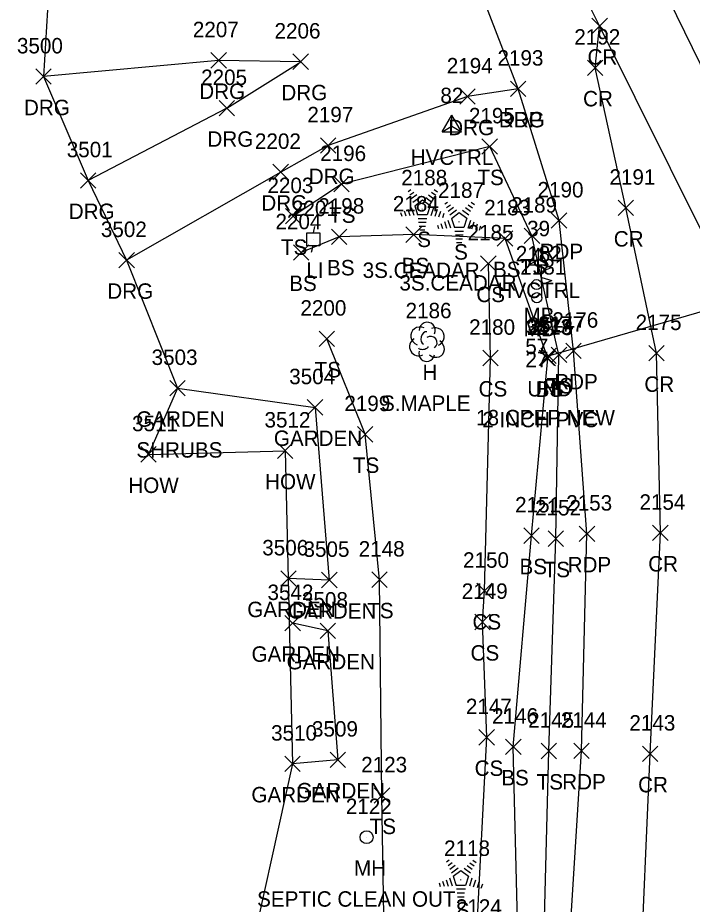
# Model space of a CAD drawing. Extents: x 1461855 to 1464118, y 556196 to 557441.
# Drawn here: x 1461866.4 to 1461953.7, y 556504.3 to 556619.2 of the extents above; entities that cross this region are included whole.
import ezdxf

# ---------------------------------------------------------------- set-up
doc = ezdxf.new("R2010")
doc.units = 0
for name, color, linetype in [('C_A', 7, 'Continuous'), ('C_I', 7, 'Continuous'), ('CPSM', 7, 'Continuous'), ('D_A', 7, 'Continuous'), ('D_C', 7, 'Continuous'), ('D_I', 7, 'Continuous'), ('D_TIC', 7, 'Continuous'), ('DCP', 7, 'Continuous'), ('L_A', 7, 'Continuous'), ('L_C', 7, 'Continuous'), ('L_I', 7, 'Continuous'), ('L_TIC', 7, 'Continuous'), ('LAPB', 7, 'Continuous'), ('LBC', 7, 'Continuous'), ('LELB', 7, 'Continuous'), ('LMB', 7, 'Continuous'), ('LSOGP', 7, 'Continuous'), ('LTC', 7, 'Continuous'), ('LTD', 7, 'Continuous'), ('P_A', 7, 'Continuous'), ('P_I', 7, 'Continuous'), ('P_TIC', 7, 'Continuous'), ('PET', 7, 'Continuous'), ('PRC', 7, 'Continuous'), ('R_A', 7, 'Continuous'), ('R_I', 7, 'Continuous'), ('R_TIC', 7, 'Continuous'), ('RDG', 7, 'Continuous'), ('U_A', 7, 'Continuous'), ('U_C', 7, 'Continuous'), ('U_I', 7, 'Continuous'), ('ULP', 7, 'Continuous'), ('UUMH', 7, 'Continuous')]:
    doc.layers.add(name, color=color, linetype=linetype)

msp = doc.modelspace()

# ---------------------------------------------------------------- linework, layer by layer
at = {"layer": 'CPSM'}
for p, q in [((1461921.33, 556604.38), (1461922.58, 556606.54)), ((1461923.83, 556604.38), (1461922.58, 556606.54)), ((1461922.58, 556605.1), (1461922.58, 556606.54)), ((1461921.33, 556604.38), (1461922.58, 556605.1)), ((1461922.58, 556605.1), (1461922.58, 556605.1)), ((1461922.58, 556605.1), (1461923.83, 556604.38)), ((1461921.33, 556604.38), (1461923.83, 556604.38)), ((1461932.57, 556587.14), (1461933.82, 556589.3)), ((1461935.07, 556587.14), (1461933.82, 556589.3)), ((1461933.82, 556587.86), (1461933.82, 556589.3)), ((1461932.57, 556587.14), (1461933.82, 556587.86)), ((1461933.82, 556587.86), (1461933.82, 556587.86)), ((1461933.82, 556587.86), (1461935.07, 556587.14)), ((1461932.57, 556587.14), (1461935.07, 556587.14))]:
    msp.add_line(p, q, dxfattribs=at)
at = {"layer": 'D_TIC'}
for points in [[(1461933.9, 556574.12), (1461935.9, 556576.12)], [(1461935.9, 556574.12), (1461933.9, 556576.12)], [(1461934.12, 556574.37), (1461936.12, 556576.37)], [(1461936.12, 556574.37), (1461934.12, 556576.37)]]:
    msp.add_lwpolyline(points, dxfattribs=at)
at = {"layer": 'DCP'}
msp.add_lwpolyline([(1461935.12, 556575.37), (1461973.52, 556586.51)], dxfattribs=at)
at = {"layer": 'L_TIC'}
for points in [[(1461926.5, 556601.48), (1461928.5, 556603.48)], [(1461928.5, 556601.48), (1461926.5, 556603.48)], [(1461907.3, 556596.6), (1461909.3, 556598.6)], [(1461909.3, 556596.6), (1461907.3, 556598.6)], [(1461901.06, 556592.45), (1461903.06, 556594.45)], [(1461903.06, 556592.45), (1461901.06, 556594.45)], [(1461916.66, 556590.07), (1461918.66, 556592.07)], [(1461918.66, 556590.07), (1461916.66, 556592.07)], [(1461907, 556589.79), (1461909, 556591.79)], [(1461909, 556589.79), (1461907, 556591.79)], [(1461928.49, 556589.57), (1461930.49, 556591.57)], [(1461930.49, 556589.57), (1461928.49, 556591.57)], [(1461931.98, 556589.92), (1461933.98, 556591.92)], [(1461933.98, 556589.92), (1461931.98, 556591.92)], [(1461902.09, 556587.77), (1461904.09, 556589.77)], [(1461904.09, 556587.77), (1461902.09, 556589.77)], [(1461926.33, 556586.33), (1461928.33, 556588.33)], [(1461928.33, 556586.33), (1461926.33, 556588.33)], [(1461905.42, 556576.58), (1461907.42, 556578.58)], [(1461907.42, 556576.58), (1461905.42, 556578.58)], [(1461926.62, 556574.1), (1461928.62, 556576.1)], [(1461928.62, 556574.1), (1461926.62, 556576.1)], [(1461934.02, 556574.06), (1461936.02, 556576.06)], [(1461936.02, 556574.06), (1461934.02, 556576.06)], [(1461935.47, 556574.5), (1461937.47, 556576.5)], [(1461937.47, 556574.5), (1461935.47, 556576.5)], [(1461886.06, 556570.19), (1461888.06, 556572.19)], [(1461888.06, 556570.19), (1461886.06, 556572.19)], [(1461903.88, 556567.7), (1461905.88, 556569.7)], [(1461905.88, 556567.7), (1461903.88, 556569.7)], [(1461910.38, 556564.21), (1461912.38, 556566.21)], [(1461912.38, 556564.21), (1461910.38, 556566.21)], [(1461882.31, 556561.61), (1461884.31, 556563.61)], [(1461884.31, 556561.61), (1461882.31, 556563.61)], [(1461900.03, 556562.09), (1461902.03, 556564.09)], [(1461902.03, 556562.09), (1461900.03, 556564.09)], [(1461931.92, 556551.09), (1461933.92, 556553.09)], [(1461933.92, 556551.09), (1461931.92, 556553.09)], [(1461935.08, 556550.7), (1461937.08, 556552.7)], [(1461937.08, 556550.7), (1461935.08, 556552.7)], [(1461900.44, 556545.53), (1461902.44, 556547.53)], [(1461902.44, 556545.53), (1461900.44, 556547.53)], [(1461905.73, 556545.34), (1461907.73, 556547.34)], [(1461907.73, 556545.34), (1461905.73, 556547.34)], [(1461912.23, 556545.38), (1461914.23, 556547.38)], [(1461914.23, 556545.38), (1461912.23, 556547.38)], [(1461925.83, 556543.93), (1461927.83, 556545.93)], [(1461927.83, 556543.93), (1461925.83, 556545.93)], [(1461900.99, 556539.75), (1461902.99, 556541.75)], [(1461902.99, 556539.75), (1461900.99, 556541.75)], [(1461925.58, 556539.9), (1461927.58, 556541.9)], [(1461927.58, 556539.9), (1461925.58, 556541.9)], [(1461905.53, 556538.77), (1461907.53, 556540.77)], [(1461907.53, 556538.77), (1461905.53, 556540.77)], [(1461926.11, 556524.97), (1461928.11, 556526.97)], [(1461928.11, 556524.97), (1461926.11, 556526.97)], [(1461929.56, 556523.74), (1461931.56, 556525.74)], [(1461931.56, 556523.74), (1461929.56, 556525.74)], [(1461934.17, 556523.2), (1461936.17, 556525.2)], [(1461936.17, 556523.2), (1461934.17, 556525.2)], [(1461900.97, 556521.54), (1461902.97, 556523.54)], [(1461902.97, 556521.54), (1461900.97, 556523.54)], [(1461906.83, 556522.06), (1461908.83, 556524.06)], [(1461908.83, 556522.06), (1461906.83, 556524.06)], [(1461912.55, 556517.43), (1461914.55, 556519.43)], [(1461914.55, 556517.43), (1461912.55, 556519.43)]]:
    msp.add_lwpolyline(points, dxfattribs=at)
at = {"layer": 'LAPB'}
for points in [[(1461887.06, 556571.19), (1461904.88, 556568.7), (1461906.73, 556546.34), (1461901.44, 556546.53)], [(1461906.53, 556539.77), (1461901.99, 556540.75)], [(1461906.53, 556539.77), (1461907.83, 556523.06), (1461901.97, 556522.54)]]:
    msp.add_lwpolyline(points, dxfattribs=at)
at = {"layer": 'LBC'}
for points in [[(1461883.31, 556562.61), (1461901.03, 556563.09)], [(1461901.03, 556563.09), (1461901.97, 556522.54)]]:
    msp.add_lwpolyline(points, dxfattribs=at)
at = {"layer": 'LELB'}
for points in [[(1461899.63, 556444.57), (1461917.51, 556446.54), (1461926.98, 556450.24), (1461930.93, 556452.9), (1461933.04, 556466.68), (1461934.48, 556497.52), (1461935.17, 556524.2), (1461936.08, 556551.7), (1461936.47, 556575.5), (1461932.98, 556590.92), (1461927.5, 556602.48), (1461908.3, 556597.6), (1461902.06, 556593.45)], [(1461926.98, 556450.24), (1461928.93, 556466.96), (1461930.54, 556495.13), (1461931.2, 556498.72), (1461930.56, 556524.74), (1461932.92, 556552.09), (1461935.02, 556575.06), (1461929.49, 556590.57), (1461917.66, 556591.07), (1461908, 556590.79), (1461903.09, 556588.77)], [(1461925.81, 556499.99), (1461927.11, 556525.97), (1461926.58, 556540.9), (1461926.83, 556544.93), (1461927.62, 556575.1), (1461927.33, 556587.33)], [(1461898.41, 556485.56), (1461911.25, 556480.99), (1461916.71, 556467.39), (1461920.73, 556483.84), (1461913.88, 556497.77), (1461913.55, 556518.43), (1461913.23, 556546.38), (1461911.38, 556565.21), (1461906.42, 556577.58)]]:
    msp.add_lwpolyline(points, dxfattribs=at)
at = {"layer": 'LMB'}
for p, q in [((1461934.23, 556587.2), (1461935.52, 556586.82)), ((1461934.23, 556584.61), (1461934.23, 556587.2)), ((1461934.23, 556586.3), (1461935.51, 556586.81)), ((1461934.25, 556585.5), (1461935.54, 556585.12)), ((1461934.25, 556582.91), (1461934.25, 556585.5)), ((1461933.58, 556584.6), (1461933.58, 556584.6)), ((1461934.25, 556584.6), (1461935.53, 556585.11)), ((1461933.6, 556582.9), (1461933.6, 556582.9))]:
    msp.add_line(p, q, dxfattribs=at)
for centre in [(1461933.58, 556584.6), (1461933.6, 556582.9)]:
    msp.add_circle(centre, 0.656, dxfattribs=at)
at = {"layer": 'LSOGP'}
msp.add_lwpolyline([(1461870.49, 556624.54), (1461869.71, 556611.54), (1461875.51, 556598.09), (1461880.49, 556587.76), (1461887.06, 556571.19), (1461883.31, 556562.61), (1461901.03, 556563.09), (1461901.97, 556522.54), (1461895.7, 556494.22)], dxfattribs=at)
at = {"layer": 'LTC'}
for p, q in [((1461916.93, 556596.67), (1461917.29, 556596.93)), ((1461920.33, 556596.91), (1461920.75, 556596.61)), ((1461917.14, 556596.21), (1461917.67, 556596.59)), ((1461917.35, 556595.74), (1461918.06, 556596.25)), ((1461917.56, 556595.28), (1461918.44, 556595.91)), ((1461917.79, 556594.82), (1461918.8, 556595.56)), ((1461918.8, 556595.56), (1461919.8, 556594.83)), ((1461919.22, 556595.87), (1461920.03, 556595.28)), ((1461919.59, 556596.22), (1461920.27, 556595.72)), ((1461919.96, 556596.56), (1461920.51, 556596.17)), ((1461916.88, 556594.39), (1461917.15, 556593.55)), ((1461917.33, 556594.6), (1461917.66, 556593.58)), ((1461917.79, 556594.82), (1461918.17, 556593.63)), ((1461919.8, 556594.83), (1461919.4, 556593.63)), ((1461920.23, 556594.56), (1461919.9, 556593.52)), ((1461920.68, 556594.31), (1461920.39, 556593.42)), ((1461921.7, 556595.04), (1461922.05, 556595.29)), ((1461921.91, 556594.57), (1461922.44, 556594.95)), ((1461922.12, 556594.1), (1461922.82, 556594.62)), ((1461924.36, 556594.58), (1461925.03, 556594.09)), ((1461924.73, 556594.93), (1461925.28, 556594.53)), ((1461925.1, 556595.28), (1461925.52, 556594.97)), ((1461915.97, 556593.95), (1461916.12, 556593.48)), ((1461916.42, 556594.17), (1461916.63, 556593.52)), ((1461919.4, 556593.63), (1461918.17, 556593.63)), ((1461921.12, 556594.06), (1461920.89, 556593.33)), ((1461921.57, 556593.81), (1461921.38, 556593.23)), ((1461922.33, 556593.64), (1461923.21, 556594.28)), ((1461922.55, 556593.18), (1461923.56, 556593.92)), ((1461922.55, 556593.18), (1461922.94, 556591.99)), ((1461923.56, 556593.92), (1461924.56, 556593.19)), ((1461923.98, 556594.23), (1461924.79, 556593.64)), ((1461924.56, 556593.19), (1461924.17, 556591.99)), ((1461919.37, 556593.13), (1461918.22, 556593.13)), ((1461919.28, 556592.63), (1461918.29, 556592.63)), ((1461919.2, 556592.13), (1461918.37, 556592.13)), ((1461920.73, 556592.31), (1461920.88, 556591.85)), ((1461921.19, 556592.53), (1461921.4, 556591.88)), ((1461921.64, 556592.75), (1461921.91, 556591.91)), ((1461922.1, 556592.96), (1461922.43, 556591.95)), ((1461925, 556592.92), (1461924.66, 556591.88)), ((1461925.44, 556592.67), (1461925.16, 556591.79)), ((1461925.89, 556592.42), (1461925.65, 556591.69)), ((1461926.33, 556592.17), (1461926.15, 556591.6)), ((1461919.11, 556591.63), (1461918.44, 556591.63)), ((1461924.17, 556591.99), (1461922.94, 556591.99)), ((1461924.13, 556591.49), (1461922.99, 556591.49)), ((1461924.05, 556590.99), (1461923.06, 556590.99)), ((1461923.96, 556590.49), (1461923.13, 556590.49)), ((1461923.88, 556589.99), (1461923.21, 556589.99)), ((1461921.91, 556509.82), (1461922.27, 556510.08)), ((1461922.12, 556509.36), (1461922.65, 556509.74)), ((1461922.33, 556508.89), (1461923.04, 556509.4)), ((1461924.57, 556509.37), (1461925.25, 556508.87)), ((1461924.94, 556509.71), (1461925.49, 556509.32)), ((1461925.31, 556510.06), (1461925.73, 556509.76)), ((1461922.54, 556508.43), (1461923.42, 556509.06)), ((1461922.77, 556507.97), (1461923.78, 556508.7)), ((1461923.78, 556508.7), (1461924.77, 556507.98)), ((1461924.2, 556509.02), (1461925.01, 556508.43)), ((1461920.95, 556507.1), (1461921.1, 556506.63)), ((1461921.4, 556507.32), (1461921.61, 556506.67)), ((1461921.86, 556507.53), (1461922.13, 556506.7)), ((1461922.31, 556507.75), (1461922.64, 556506.73)), ((1461922.77, 556507.97), (1461923.15, 556506.78)), ((1461924.77, 556507.98), (1461924.38, 556506.78)), ((1461925.21, 556507.71), (1461924.87, 556506.67)), ((1461925.66, 556507.46), (1461925.37, 556506.57)), ((1461926.1, 556507.21), (1461925.86, 556506.48)), ((1461924.38, 556506.78), (1461923.15, 556506.78)), ((1461924.35, 556506.28), (1461923.2, 556506.28)), ((1461926.55, 556506.96), (1461926.36, 556506.38)), ((1461924.26, 556505.78), (1461923.27, 556505.78)), ((1461924.18, 556505.28), (1461923.35, 556505.28)), ((1461924.09, 556504.78), (1461923.42, 556504.78))]:
    msp.add_line(p, q, dxfattribs=at)
at = {"layer": 'LTD'}
msp.add_line((1461919.36, 556577.24), (1461919.36, 556577.24), dxfattribs=at)
msp.add_line((1461919.36, 556577.24), (1461919.36, 556577.24), dxfattribs=at)
msp.add_arc((1461919.41, 556578.67), 1.05, 335.5272, 180.9563, dxfattribs=at)
for centre, major_axis, ratio, start_param, end_param in [((1461918.57, 556577.9), (1.21, -0.51), 0.895232, 1.570796, 4.712389), ((1461919.15, 556577.69), (-0.208, -0.792), 0.645439, 3.141593, 6.283185), ((1461920.4, 556577.82), (-1.14, -0.48), 0.949671, 1.570796, 4.712389), ((1461918.28, 556576.53), (0.58, -1.04), 0.959034, 3.141593, 6.283185), ((1461919.86, 556577.07), (-0.5, 0.667), 0.989748, 3.141593, 6.283185), ((1461920.36, 556576.4), (-1.09, 0.79), 0.841452, 1.570796, 4.712389), ((1461919.36, 556575.74), (0.26, 1.06), 0.942809, 1.570796, 4.712389), ((1461918.9, 556576.49), (-0.625, -0.083), 0.423636, 0, 3.141593)]:
    msp.add_ellipse(centre, major_axis=major_axis, ratio=ratio, start_param=start_param, end_param=end_param, dxfattribs=at)
at = {"layer": 'P_TIC'}
for points in [[(1461940.74, 556617.09), (1461942.74, 556619.09)], [(1461942.74, 556617.09), (1461940.74, 556619.09)], [(1461940.74, 556617.09), (1461942.74, 556619.09)], [(1461942.74, 556617.09), (1461940.74, 556619.09)], [(1461940.15, 556611.68), (1461942.15, 556613.68)], [(1461942.15, 556611.68), (1461940.15, 556613.68)], [(1461930.2, 556608.96), (1461932.2, 556610.96)], [(1461932.2, 556608.96), (1461930.2, 556610.96)], [(1461944.13, 556593.53), (1461946.13, 556595.53)], [(1461946.13, 556593.53), (1461944.13, 556595.53)], [(1461935.48, 556591.89), (1461937.48, 556593.89)], [(1461937.48, 556591.89), (1461935.48, 556593.89)], [(1461937.36, 556575.02), (1461939.36, 556577.02)], [(1461939.36, 556575.02), (1461937.36, 556577.02)], [(1461948.09, 556574.71), (1461950.09, 556576.71)], [(1461950.09, 556574.71), (1461948.09, 556576.71)], [(1461939.1, 556551.33), (1461941.1, 556553.33)], [(1461941.1, 556551.33), (1461939.1, 556553.33)], [(1461948.6, 556551.44), (1461950.6, 556553.44)], [(1461950.6, 556551.44), (1461948.6, 556553.44)], [(1461938.4, 556523.21), (1461940.4, 556525.21)], [(1461940.4, 556523.21), (1461938.4, 556525.21)], [(1461947.29, 556522.84), (1461949.29, 556524.84)], [(1461949.29, 556522.84), (1461947.29, 556524.84)]]:
    msp.add_lwpolyline(points, dxfattribs=at)
at = {"layer": 'PET'}
for points in [[(1461941.43, 556640.49), (1461960.91, 556600.59), (1461969.59, 556584.05), (1461984.63, 556553.38), (1461998.6, 556528.82), (1462012.32, 556509.4), (1462030.27, 556491.56), (1462047.25, 556480.46), (1462067.72, 556469.89), (1462084.83, 556462.24), (1462093.33, 556458.86), (1462104, 556455.55), (1462122, 556451.36), (1462134.06, 556450.12), (1462148.83, 556449.19)], [(1461914.87, 556308.56), (1461920.44, 556347.39), (1461926.93, 556386.33), (1461932.33, 556425.02), (1461933.9, 556440.31), (1461936.11, 556466.53), (1461937.59, 556495.16), (1461939.4, 556524.21), (1461940.1, 556552.33), (1461938.36, 556576.02), (1461936.48, 556592.89), (1461931.2, 556609.96), (1461922.6, 556632.21)]]:
    msp.add_lwpolyline(points, dxfattribs=at)
at = {"layer": 'PRC'}
for points in [[(1461932.21, 556637.12), (1461941.74, 556618.09)], [(1461925.46, 556305.98), (1461931.48, 556345.96), (1461937.93, 556386.44), (1461943.12, 556427.08), (1461945.49, 556465.38), (1461946.96, 556493.02), (1461948.29, 556523.84), (1461949.6, 556552.44), (1461949.09, 556575.71), (1461945.13, 556594.53), (1461941.15, 556612.68), (1461941.74, 556618.09), (1461960.04, 556581.27), (1461976.53, 556548.03), (1461990.31, 556523.95), (1462006.12, 556501.89), (1462023.43, 556483.27), (1462041.85, 556469.09), (1462061.76, 556457.44), (1462082.72, 556450.2), (1462107.82, 556443.98), (1462129.57, 556440.39), (1462147.93, 556438.2)]]:
    msp.add_lwpolyline(points, dxfattribs=at)
at = {"layer": 'R_TIC'}
for points in [[(1461891.4, 556612.64), (1461893.4, 556614.64)], [(1461893.4, 556612.64), (1461891.4, 556614.64)], [(1461902.03, 556612.47), (1461904.03, 556614.47)], [(1461904.03, 556612.47), (1461902.03, 556614.47)], [(1461868.71, 556610.54), (1461870.71, 556612.54)], [(1461870.71, 556610.54), (1461868.71, 556612.54)], [(1461930.2, 556608.96), (1461932.2, 556610.96)], [(1461932.2, 556608.96), (1461930.2, 556610.96)], [(1461923.64, 556607.95), (1461925.64, 556609.95)], [(1461925.64, 556607.95), (1461923.64, 556609.95)], [(1461892.47, 556606.45), (1461894.47, 556608.45)], [(1461894.47, 556606.45), (1461892.47, 556608.45)], [(1461905.59, 556601.62), (1461907.59, 556603.62)], [(1461907.59, 556601.62), (1461905.59, 556603.62)], [(1461899.44, 556598.18), (1461901.44, 556600.18)], [(1461901.44, 556598.18), (1461899.44, 556600.18)], [(1461874.51, 556597.09), (1461876.51, 556599.09)], [(1461876.51, 556597.09), (1461874.51, 556599.09)], [(1461879.49, 556586.76), (1461881.49, 556588.76)], [(1461881.49, 556586.76), (1461879.49, 556588.76)]]:
    msp.add_lwpolyline(points, dxfattribs=at)
at = {"layer": 'RDG'}
for points in [[(1461892.4, 556613.64), (1461869.71, 556611.54)], [(1461893.47, 556607.45), (1461903.03, 556613.47), (1461892.4, 556613.64)], [(1461931.2, 556609.96), (1461924.64, 556608.95), (1461906.59, 556602.62), (1461900.44, 556599.18)], [(1461893.47, 556607.45), (1461875.51, 556598.09)], [(1461900.44, 556599.18), (1461880.49, 556587.76)]]:
    msp.add_lwpolyline(points, dxfattribs=at)
at = {"layer": 'ULP'}
for p, q in [((1461904.82, 556592.13), (1461904.66, 556591.3)), ((1461903.82, 556589.63), (1461903.82, 556591.3)), ((1461903.82, 556591.3), (1461905.49, 556591.3)), ((1461905.49, 556591.3), (1461905.49, 556589.63)), ((1461904.66, 556590.47), (1461904.66, 556590.47)), ((1461905.49, 556589.63), (1461903.82, 556589.63)), ((1461904.41, 556588.8), (1461904.66, 556589.63))]:
    msp.add_line(p, q, dxfattribs=at)
at = {"layer": 'UUMH'}
for p, q in [((1461911.56, 556513.03), (1461911.56, 556513.03)), ((1461912.4, 556513.03), (1461912.4, 556513.03))]:
    msp.add_line(p, q, dxfattribs=at)
msp.add_circle((1461911.56, 556513.03), 0.833, dxfattribs=at)

# ---------------------------------------------------------------- texts
at = {"layer": 'C_A'}
for p in [(1461917.27, 556600.1), (1461928.51, 556582.86)]:
    msp.add_text('HVCTRL', height=2, dxfattribs=at).set_placement(p)
at = {"layer": 'C_I'}
for s, p in [('82', (1461921.11, 556608.1)), ('39', (1461932.35, 556590.86))]:
    msp.add_text(s, height=2, dxfattribs=at).set_placement(p)
at = {"layer": 'D_A'}
for s, p in [('UND', (1461932.37, 556570.12)), ('P', (1461934.5, 556570.37))]:
    msp.add_text(s, height=2, dxfattribs=at).set_placement(p)
at = {"layer": 'D_C'}
for s, p in [('18 CPEP NEW', (1461925.74, 556566.37)), ('2 INCH PVC', (1461926.55, 556566.12))]:
    msp.add_text(s, height=2, dxfattribs=at).set_placement(p)
at = {"layer": 'D_I'}
for s, p in [('3513', (1461932.21, 556578.12)), ('3514', (1461932.43, 556578.37))]:
    msp.add_text(s, height=2, dxfattribs=at).set_placement(p)
at = {"layer": 'L_A'}
for s, p in [('TS', (1461925.91, 556597.48)), ('TS', (1461906.71, 556592.6)), ('S', (1461918.12, 556589.46)), ('TS', (1461900.47, 556588.45)), ('S', (1461922.89, 556587.83)), ('BS', (1461906.44, 556585.79)), ('BS', (1461916.1, 556586.07)), ('BS', (1461927.93, 556585.57)), ('TS', (1461931.39, 556585.92)), ('BS', (1461901.54, 556583.77)), ('CS', (1461925.77, 556582.33)), ('MB', (1461931.88, 556579.6)), ('MB', (1461931.9, 556577.9)), ('TS', (1461904.83, 556572.58)), ('H', (1461918.8, 556572.24)), ('TS', (1461934.88, 556570.5)), ('CS', (1461926.06, 556570.1)), ('BS', (1461933.46, 556570.06)), ('GARDEN', (1461881.73, 556566.19)), ('GARDEN', (1461899.55, 556563.7)), ('TS', (1461909.79, 556560.21)), ('HOW', (1461898.42, 556558.09)), ('HOW', (1461880.7, 556557.61)), ('BS', (1461931.36, 556547.09)), ('TS', (1461934.49, 556546.7)), ('GARDEN', (1461896.11, 556541.53)), ('GARDEN', (1461901.39, 556541.34)), ('TS', (1461911.64, 556541.38)), ('CS', (1461925.27, 556539.93)), ('GARDEN', (1461896.66, 556535.75)), ('CS', (1461925.02, 556535.9)), ('GARDEN', (1461901.2, 556534.77)), ('CS', (1461925.55, 556520.97)), ('BS', (1461929, 556519.74)), ('TS', (1461933.58, 556519.2)), ('GARDEN', (1461902.5, 556518.06)), ('GARDEN', (1461896.64, 556517.54)), ('TS', (1461911.96, 556513.43)), ('S', (1461923.1, 556502.61))]:
    msp.add_text(s, height=2, dxfattribs=at).set_placement(p)
at = {"layer": 'L_C'}
for s, p in [('3S.CEADAR', (1461911.05, 556585.46)), ('3S.CEADAR', (1461915.81, 556583.83)), ('57', (1461932.11, 556575.6)), ('27', (1461932.13, 556573.9)), ('S.MAPLE', (1461913.43, 556568.24)), ('SHRUBS', (1461881.75, 556562.19))]:
    msp.add_text(s, height=2, dxfattribs=at).set_placement(p)
at = {"layer": 'L_I'}
for s, p in [('2195', (1461924.81, 556605.48)), ('2196', (1461905.55, 556600.6)), ('2188', (1461916.05, 556597.46)), ('2203', (1461898.72, 556596.45)), ('2187', (1461920.81, 556595.83)), ('2198', (1461905.3, 556593.79)), ('2184', (1461914.96, 556594.07)), ('2183', (1461926.79, 556593.57)), ('2189', (1461930.27, 556593.92)), ('2204', (1461899.76, 556591.77)), ('2185', (1461924.64, 556590.33)), ('2182', (1461930.88, 556587.6)), ('2181', (1461931.47, 556585.9)), ('2200', (1461902.99, 556580.58)), ('2186', (1461916.61, 556580.24)), ('2177', (1461933.78, 556578.5)), ('2180', (1461924.84, 556578.1)), ('2178', (1461932.33, 556578.06)), ('3503', (1461883.72, 556574.19)), ('3504', (1461901.54, 556571.7)), ('2199', (1461908.68, 556568.21)), ('3512', (1461898.34, 556566.09)), ('3511', (1461881.19, 556565.61)), ('2151', (1461930.79, 556555.09)), ('2152', (1461933.38, 556554.7)), ('3506', (1461898.05, 556549.53)), ('3505', (1461903.39, 556549.34)), ('2148', (1461910.54, 556549.38)), ('2150', (1461924.05, 556547.93)), ('3542', (1461898.73, 556543.75)), ('2149', (1461923.88, 556543.9)), ('3508', (1461903.19, 556542.77)), ('2147', (1461924.42, 556528.97)), ('2146', (1461927.81, 556527.74)), ('2145', (1461932.48, 556527.2)), ('3509', (1461904.49, 556526.06)), ('3510', (1461899.19, 556525.54)), ('2123', (1461910.86, 556521.43)), ('2118', (1461921.59, 556510.61)), ('2124', (1461923.12, 556502.99))]:
    msp.add_text(s, height=2, dxfattribs=at).set_placement(p)
at = {"layer": 'LTC'}
for p in [(1461918.68, 556594.57), (1461923.45, 556592.93), (1461923.66, 556507.72)]:
    msp.add_text('.', height=1.04, rotation=270, dxfattribs=at).set_placement(p)
at = {"layer": 'P_A'}
for s, p in [('CR', (1461940.17, 556613.09)), ('CR', (1461940.17, 556613.09)), ('CR', (1461939.59, 556607.68)), ('RDP', (1461928.69, 556604.96)), ('CR', (1461943.57, 556589.53)), ('RDP', (1461933.96, 556587.89)), ('RDP', (1461935.85, 556571.02)), ('CR', (1461947.53, 556570.71)), ('RDP', (1461937.59, 556547.33)), ('CR', (1461948.03, 556547.44)), ('RDP', (1461936.89, 556519.21)), ('CR', (1461946.72, 556518.84))]:
    msp.add_text(s, height=2, dxfattribs=at).set_placement(p)
at = {"layer": 'P_I'}
for s, p in [('2192', (1461938.46, 556615.68)), ('2193', (1461928.51, 556612.96)), ('2191', (1461943.01, 556597.53)), ('2190', (1461933.7, 556595.89)), ('2176', (1461935.61, 556579.02)), ('2175', (1461946.4, 556578.71)), ('2153', (1461937.41, 556555.33)), ('2154', (1461946.9, 556555.44)), ('2144', (1461936.71, 556527.21)), ('2143', (1461945.59, 556526.84))]:
    msp.add_text(s, height=2, dxfattribs=at).set_placement(p)
at = {"layer": 'R_A'}
for p in [(1461889.89, 556608.64), (1461900.52, 556608.47), (1461867.19, 556606.54), (1461928.69, 556604.96), (1461922.13, 556603.95), (1461890.95, 556602.45), (1461904.07, 556597.62), (1461897.93, 556594.18), (1461872.99, 556593.09), (1461877.98, 556582.76)]:
    msp.add_text('DRG', height=2, dxfattribs=at).set_placement(p)
at = {"layer": 'R_I'}
for s, p in [('2207', (1461889.06, 556616.64)), ('2206', (1461899.64, 556616.47)), ('3500', (1461866.28, 556614.54)), ('2193', (1461928.51, 556612.96)), ('2194', (1461921.94, 556611.95)), ('2205', (1461890.13, 556610.45)), ('2197', (1461903.89, 556605.62)), ('2202', (1461897.1, 556602.18)), ('3501', (1461872.73, 556601.09)), ('3502', (1461877.15, 556590.76))]:
    msp.add_text(s, height=2, dxfattribs=at).set_placement(p)
at = {"layer": 'U_A'}
for s, p in [('LI', (1461903.76, 556585.47)), ('MH', (1461909.93, 556508.03))]:
    msp.add_text(s, height=2, dxfattribs=at).set_placement(p)
at = {"layer": 'U_C'}
msp.add_text('SEPTIC CLEAN OUT', height=2, dxfattribs=at).set_placement((1461897.38, 556504.03))
at = {"layer": 'U_I'}
for s, p in [('2201', (1461901.89, 556593.47)), ('2122', (1461908.87, 556516.03))]:
    msp.add_text(s, height=2, dxfattribs=at).set_placement(p)

doc.saveas('drawing.dxf')
